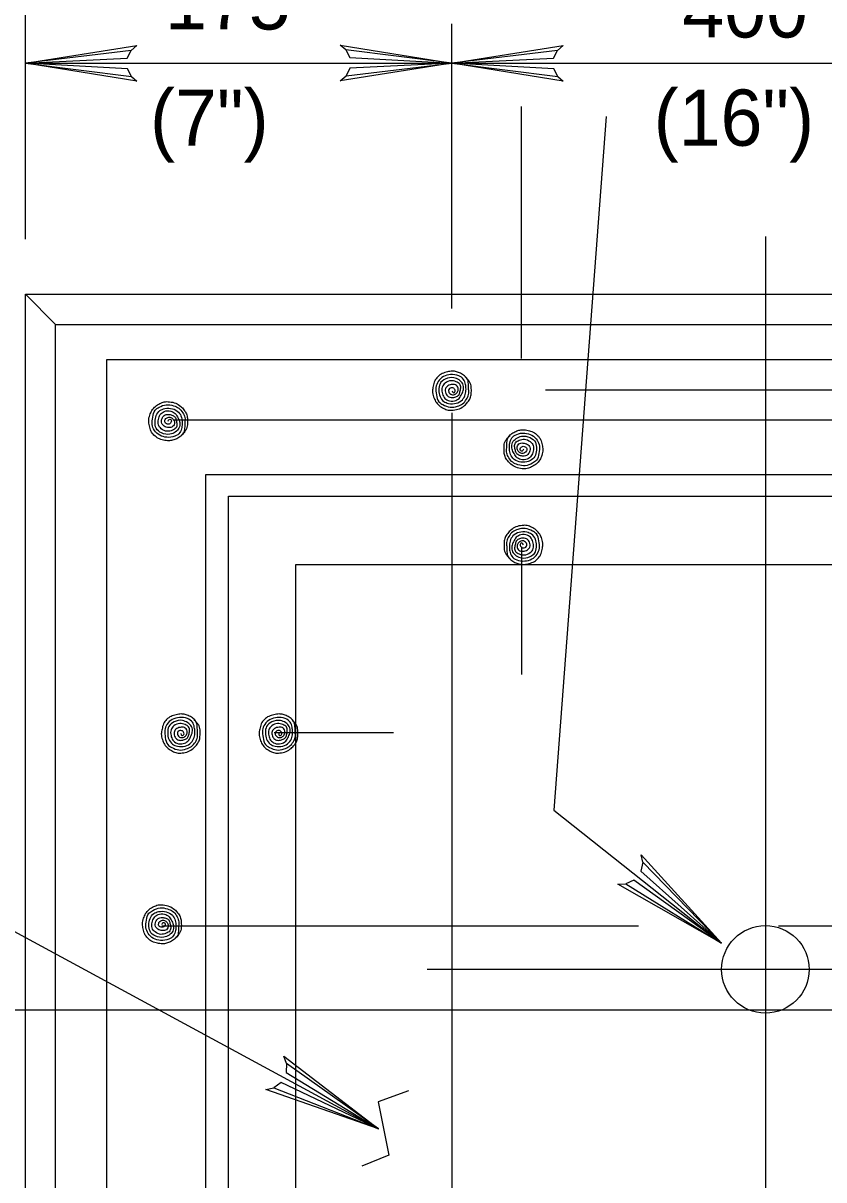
# Model space of a CAD drawing. Extents: x 638455 to 640199, y 298558 to 299152.
# Drawn here: x 639455 to 639502.8, y 299012.9 to 299082 of the extents above; entities that cross this region are included whole.
import ezdxf

# ---------------------------------------------------------------- set-up
doc = ezdxf.new("R2010")
doc.units = 0
for name, color, linetype in [('1', 7, 'Continuous'), ('2', 7, 'Continuous'), ('3', 7, 'Continuous')]:
    doc.layers.add(name, color=color, linetype=linetype)

msp = doc.modelspace()

# ---------------------------------------------------------------- linework, layer by layer
at = {"layer": '1'}
for points in [[(639491.985, 299031.846), (639491.878, 299031.311), (639496.699, 299027.013), (639491.985, 299031.846), (639491.9, 299032.29), (639496.699, 299027.013), (639491.461, 299030.78), (639490.978, 299030.552), (639496.699, 299027.013), (639490.495, 299030.528), (639490.978, 299030.552)], [(639470.711, 299019.827), (639470.701, 299019.282), (639476.213, 299015.916), (639470.711, 299019.827), (639470.548, 299020.249), (639476.213, 299015.916), (639470.386, 299018.685), (639469.952, 299018.374), (639476.213, 299015.916), (639469.481, 299018.263), (639469.952, 299018.374)], [(639478.001, 299018.178), (639476.18, 299017.527), (639476.83, 299014.338), (639475.204, 299013.687)]]:
    msp.add_lwpolyline(points, dxfattribs=at)
at = {"layer": '2'}
for p, q in [((639455.114, 299069.069), (639455.114, 299092.486)), ((639480.579, 299064.94), (639480.579, 299081.944)), ((639455.114, 299079.596), (639480.579, 299079.596)), ((639480.579, 299079.596), (639518.052, 299079.596)), ((639484.748, 299061.942), (639484.748, 299077.013)), ((639489.813, 299076.401), (639486.672, 299034.951)), ((639499.316, 299069.23), (639499.316, 298997.046)), ((639456.919, 299063.987), (639455.114, 299065.791)), ((639455.114, 298964.165), (639455.114, 299065.791)), ((639455.114, 299065.791), (639543.517, 299065.791)), ((639456.919, 298964.165), (639456.919, 299063.987)), ((639459.977, 298949.406), (639459.977, 299061.884)), ((639486.183, 299060.066), (639511.411, 299060.066)), ((639463.941, 299058.292), (639535.345, 299058.292)), ((639480.579, 299058.705), (639480.579, 299000.251)), ((639465.9, 299055.006), (639532.731, 299055.006)), ((639465.9, 298956.209), (639465.9, 299055.006)), ((639467.242, 299053.726), (639531.389, 299053.726)), ((639467.242, 298957.614), (639467.242, 299053.726)), ((639484.748, 299050.686), (639484.748, 299043.062)), ((639471.267, 299049.639), (639527.364, 299049.639)), ((639469.97, 299039.596), (639477.095, 299039.596)), ((639486.672, 299034.951), (639496.699, 299027.013)), ((639449.145, 299030.573), (639476.213, 299015.917)), ((639463.258, 299028.043), (639491.743, 299028.043)), ((639500.102, 299028.043), (639535.572, 299028.043)), ((639518.499, 299025.445), (639479.119, 299025.445)), ((639373.945, 299023.031), (639513.286, 299023.031))]:
    msp.add_line(p, q, dxfattribs=at)
for points in [[(639461.445, 299078.803), (639461.207, 299079.259), (639455.114, 299079.596), (639461.445, 299078.803), (639461.767, 299078.524), (639455.114, 299079.596), (639461.204, 299079.897), (639461.425, 299080.351), (639455.114, 299079.596), (639461.767, 299080.652), (639461.425, 299080.351)], [(639474.248, 299080.391), (639474.486, 299079.933), (639480.579, 299079.596), (639474.248, 299080.391), (639473.926, 299080.67), (639480.579, 299079.596), (639474.489, 299079.296), (639474.268, 299078.841), (639480.579, 299079.596), (639473.926, 299078.539), (639474.268, 299078.841)], [(639486.91, 299078.803), (639486.671, 299079.259), (639480.579, 299079.596), (639486.91, 299078.803), (639487.232, 299078.524), (639480.579, 299079.596), (639486.668, 299079.897), (639486.889, 299080.351), (639480.579, 299079.596), (639487.232, 299080.652), (639486.889, 299080.351)], [(639456.919, 299063.987), (639543.517, 299063.987)], [(639459.977, 299061.884), (639511.013, 299061.884)], [(639471.267, 298961.576), (639471.267, 299049.639)]]:
    msp.add_lwpolyline(points, dxfattribs=at)
msp.add_circle((639499.315, 299025.445), 2.614, dxfattribs=at)
for points in [[(639480.597, 299060.023), (639480.658, 299059.907), (639480.746, 299059.922), (639480.763, 299060.104), (639480.603, 299060.2), (639480.406, 299060.104), (639480.415, 299059.922), (639480.522, 299059.808), (639480.746, 299059.791), (639480.896, 299059.907), (639480.972, 299060.096), (639480.862, 299060.343), (639480.621, 299060.398), (639480.354, 299060.317), (639480.211, 299060.148), (639480.229, 299059.864), (639480.362, 299059.681), (639480.603, 299059.614), (639480.818, 299059.657), (639480.995, 299059.765), (639481.071, 299059.951), (639481.117, 299060.192), (639481.062, 299060.416), (639480.853, 299060.558), (639480.531, 299060.621), (639480.185, 299060.479), (639480.011, 299060.238), (639480.011, 299059.907), (639480.121, 299059.625), (639480.362, 299059.44), (639480.746, 299059.416), (639481.018, 299059.567), (639481.184, 299059.832), (639481.283, 299060.104), (639481.236, 299060.433), (639481.018, 299060.665), (639480.702, 299060.799), (639480.197, 299060.72), (639479.88, 299060.441), (639479.813, 299060.058), (639479.88, 299059.681), (639480.101, 299059.385), (639480.394, 299059.265), (639480.853, 299059.274), (639481.216, 299059.483), (639481.387, 299059.791), (639481.434, 299060.116), (639481.402, 299060.398), (639481.292, 299060.7), (639480.995, 299060.915), (639480.513, 299060.982), (639480.086, 299060.862), (639479.77, 299060.566), (639479.639, 299060.218), (639479.671, 299059.777), (639479.813, 299059.364), (639480.054, 299059.19), (639480.478, 299059.036), (639480.92, 299059.1), (639481.228, 299059.242), (639481.463, 299059.515), (639481.591, 299059.8), (639481.591, 299060.104), (639481.576, 299060.433), (639481.501, 299060.741), (639481.344, 299060.915), (639481.103, 299061.066), (639480.862, 299061.156), (639480.621, 299061.191), (639480.319, 299061.147), (639480.011, 299061.048), (639479.747, 299060.854), (639479.564, 299060.604), (639479.474, 299060.29), (639479.43, 299059.997), (639479.497, 299059.657), (639479.619, 299059.385), (639479.837, 299059.135), (639480.101, 299058.966), (639480.362, 299058.868), (639480.676, 299058.859), (639481.042, 299058.949), (639481.344, 299059.135), (639481.53, 299059.332), (639481.686, 299059.582), (639481.742, 299059.843), (639481.75, 299060.148), (639481.686, 299060.479), (639481.591, 299060.63), (639481.387, 299060.854)], [(639463.651, 299058.196), (639463.709, 299058.312), (639463.796, 299058.3), (639463.813, 299058.117), (639463.654, 299058.019), (639463.459, 299058.117), (639463.468, 299058.3), (639463.575, 299058.411), (639463.796, 299058.428), (639463.95, 299058.312), (639464.025, 299058.126), (639463.912, 299057.877), (639463.671, 299057.821), (639463.404, 299057.903), (639463.261, 299058.071), (639463.279, 299058.359), (639463.412, 299058.542), (639463.654, 299058.608), (639463.869, 299058.562), (639464.046, 299058.454), (639464.121, 299058.269), (639464.167, 299058.028), (639464.112, 299057.804), (639463.903, 299057.662), (639463.584, 299057.601), (639463.235, 299057.743), (639463.061, 299057.984), (639463.061, 299058.312), (639463.172, 299058.594), (639463.412, 299058.783), (639463.796, 299058.803), (639464.069, 299058.652), (639464.234, 299058.388), (639464.333, 299058.117), (639464.287, 299057.787), (639464.069, 299057.554), (639463.752, 299057.42), (639463.247, 299057.502), (639462.93, 299057.778), (639462.864, 299058.161), (639462.93, 299058.542), (639463.151, 299058.835), (639463.444, 299058.954), (639463.903, 299058.945), (639464.266, 299058.736), (639464.441, 299058.428), (639464.484, 299058.103), (639464.452, 299057.821), (639464.342, 299057.519), (639464.046, 299057.304), (639463.564, 299057.238), (639463.137, 299057.36), (639462.82, 299057.653), (639462.689, 299058.001), (639462.721, 299058.443), (639462.864, 299058.858), (639463.105, 299059.032), (639463.529, 299059.184), (639463.97, 299059.119), (639464.278, 299058.977), (639464.516, 299058.704), (639464.641, 299058.42), (639464.641, 299058.117), (639464.626, 299057.787), (639464.551, 299057.479), (639464.394, 299057.304), (639464.153, 299057.153), (639463.912, 299057.064), (639463.671, 299057.028), (639463.369, 299057.072), (639463.061, 299057.171), (639462.797, 299057.369), (639462.614, 299057.618), (639462.527, 299057.929), (639462.48, 299058.225), (639462.547, 299058.562), (639462.669, 299058.835), (639462.887, 299059.085), (639463.151, 299059.253), (639463.412, 299059.352), (639463.726, 299059.36), (639464.092, 299059.273), (639464.394, 299059.085), (639464.583, 299058.887), (639464.737, 299058.637), (639464.792, 299058.376), (639464.801, 299058.071), (639464.737, 299057.743), (639464.641, 299057.589), (639464.441, 299057.369)], [(639484.857, 299056.524), (639484.796, 299056.408), (639484.709, 299056.422), (639484.691, 299056.605), (639484.851, 299056.701), (639485.049, 299056.605), (639485.04, 299056.422), (639484.933, 299056.309), (639484.709, 299056.291), (639484.558, 299056.408), (639484.482, 299056.596), (639484.593, 299056.843), (639484.834, 299056.898), (639485.101, 299056.817), (639485.243, 299056.648), (639485.226, 299056.364), (639485.092, 299056.181), (639484.851, 299056.114), (639484.636, 299056.158), (639484.459, 299056.265), (639484.384, 299056.451), (639484.337, 299056.692), (639484.392, 299056.916), (639484.601, 299057.058), (639484.924, 299057.122), (639485.269, 299056.98), (639485.444, 299056.739), (639485.444, 299056.408), (639485.333, 299056.126), (639485.092, 299055.94), (639484.709, 299055.917), (639484.436, 299056.068), (639484.27, 299056.332), (639484.172, 299056.605), (639484.218, 299056.933), (639484.436, 299057.165), (639484.752, 299057.299), (639485.258, 299057.221), (639485.574, 299056.942), (639485.641, 299056.559), (639485.574, 299056.181), (639485.354, 299055.885), (639485.06, 299055.766), (639484.601, 299055.774), (639484.238, 299055.983), (639484.067, 299056.291), (639484.021, 299056.617), (639484.053, 299056.898), (639484.163, 299057.2), (639484.459, 299057.415), (639484.941, 299057.482), (639485.368, 299057.363), (639485.685, 299057.067), (639485.816, 299056.718), (639485.783, 299056.277), (639485.641, 299055.864), (639485.4, 299055.69), (639484.976, 299055.537), (639484.535, 299055.6), (639484.227, 299055.743), (639483.992, 299056.016), (639483.864, 299056.3), (639483.864, 299056.605), (639483.878, 299056.933), (639483.954, 299057.241), (639484.111, 299057.415), (639484.352, 299057.566), (639484.593, 299057.657), (639484.834, 299057.691), (639485.136, 299057.648), (639485.444, 299057.549), (639485.708, 299057.354), (639485.891, 299057.105), (639485.981, 299056.791), (639486.025, 299056.497), (639485.958, 299056.158), (639485.836, 299055.885), (639485.618, 299055.635), (639485.354, 299055.467), (639485.092, 299055.368), (639484.779, 299055.359), (639484.413, 299055.449), (639484.111, 299055.635), (639483.925, 299055.833), (639483.768, 299056.082), (639483.713, 299056.344), (639483.704, 299056.648), (639483.768, 299056.98), (639483.864, 299057.131), (639484.067, 299057.354)], [(639484.857, 299050.806), (639484.796, 299050.922), (639484.709, 299050.907), (639484.691, 299050.725), (639484.851, 299050.629), (639485.049, 299050.725), (639485.04, 299050.907), (639484.933, 299051.021), (639484.709, 299051.038), (639484.558, 299050.922), (639484.482, 299050.733), (639484.593, 299050.486), (639484.834, 299050.431), (639485.101, 299050.513), (639485.243, 299050.681), (639485.226, 299050.966), (639485.092, 299051.149), (639484.851, 299051.215), (639484.636, 299051.172), (639484.459, 299051.064), (639484.384, 299050.878), (639484.337, 299050.638), (639484.392, 299050.414), (639484.601, 299050.272), (639484.924, 299050.208), (639485.269, 299050.35), (639485.444, 299050.591), (639485.444, 299050.922), (639485.333, 299051.204), (639485.092, 299051.39), (639484.709, 299051.413), (639484.436, 299051.262), (639484.27, 299050.998), (639484.172, 299050.725), (639484.218, 299050.397), (639484.436, 299050.164), (639484.752, 299050.031), (639485.258, 299050.109), (639485.574, 299050.388), (639485.641, 299050.771), (639485.574, 299051.149), (639485.354, 299051.445), (639485.06, 299051.564), (639484.601, 299051.555), (639484.238, 299051.346), (639484.067, 299051.038), (639484.021, 299050.713), (639484.053, 299050.431), (639484.163, 299050.129), (639484.459, 299049.914), (639484.941, 299049.848), (639485.368, 299049.967), (639485.685, 299050.263), (639485.816, 299050.611), (639485.783, 299051.053), (639485.641, 299051.465), (639485.4, 299051.639), (639484.976, 299051.793), (639484.535, 299051.729), (639484.227, 299051.587), (639483.992, 299051.314), (639483.864, 299051.03), (639483.864, 299050.725), (639483.878, 299050.397), (639483.954, 299050.089), (639484.111, 299049.914), (639484.352, 299049.763), (639484.593, 299049.673), (639484.834, 299049.639), (639485.136, 299049.682), (639485.444, 299049.781), (639485.708, 299049.975), (639485.891, 299050.225), (639485.981, 299050.539), (639486.025, 299050.832), (639485.958, 299051.172), (639485.836, 299051.445), (639485.618, 299051.695), (639485.354, 299051.863), (639485.092, 299051.962), (639484.779, 299051.971), (639484.413, 299051.88), (639484.111, 299051.695), (639483.925, 299051.497), (639483.768, 299051.248), (639483.713, 299050.986), (639483.704, 299050.681), (639483.768, 299050.35), (639483.864, 299050.199), (639484.067, 299049.975)], [(639464.403, 299039.539), (639464.461, 299039.423), (639464.549, 299039.438), (639464.569, 299039.621), (639464.406, 299039.716), (639464.211, 299039.621), (639464.22, 299039.438), (639464.328, 299039.325), (639464.549, 299039.307), (639464.703, 299039.423), (639464.778, 299039.612), (639464.665, 299039.862), (639464.423, 299039.914), (639464.156, 299039.833), (639464.014, 299039.664), (639464.032, 299039.38), (639464.165, 299039.197), (639464.406, 299039.13), (639464.621, 299039.173), (639464.798, 299039.281), (639464.877, 299039.467), (639464.92, 299039.708), (639464.865, 299039.931), (639464.656, 299040.073), (639464.337, 299040.138), (639463.988, 299039.995), (639463.814, 299039.754), (639463.814, 299039.423), (639463.924, 299039.141), (639464.165, 299038.955), (639464.549, 299038.932), (639464.821, 299039.083), (639464.987, 299039.347), (639465.086, 299039.621), (639465.039, 299039.949), (639464.821, 299040.181), (639464.505, 299040.315), (639463.999, 299040.236), (639463.683, 299039.957), (639463.616, 299039.574), (639463.683, 299039.197), (639463.904, 299038.9), (639464.197, 299038.781), (639464.656, 299038.79), (639465.019, 299038.999), (639465.193, 299039.307), (639465.237, 299039.632), (639465.205, 299039.914), (639465.094, 299040.216), (639464.798, 299040.431), (639464.319, 299040.498), (639463.889, 299040.378), (639463.573, 299040.082), (639463.442, 299039.737), (639463.474, 299039.295), (639463.616, 299038.88), (639463.857, 299038.706), (639464.281, 299038.555), (639464.723, 299038.616), (639465.03, 299038.758), (639465.269, 299039.031), (639465.393, 299039.316), (639465.393, 299039.621), (639465.379, 299039.949), (639465.303, 299040.257), (639465.146, 299040.431), (639464.906, 299040.582), (639464.665, 299040.672), (639464.423, 299040.707), (639464.122, 299040.663), (639463.814, 299040.565), (639463.549, 299040.37), (639463.367, 299040.12), (639463.279, 299039.806), (639463.233, 299039.513), (639463.3, 299039.173), (639463.422, 299038.9), (639463.639, 299038.651), (639463.904, 299038.482), (639464.165, 299038.383), (639464.479, 299038.375), (639464.845, 299038.465), (639465.146, 299038.651), (639465.335, 299038.848), (639465.489, 299039.098), (639465.545, 299039.362), (639465.553, 299039.664), (639465.489, 299039.995), (639465.393, 299040.146), (639465.193, 299040.37)], [(639470.244, 299039.539), (639470.302, 299039.423), (639470.389, 299039.438), (639470.409, 299039.621), (639470.246, 299039.716), (639470.052, 299039.621), (639470.06, 299039.438), (639470.168, 299039.325), (639470.389, 299039.307), (639470.543, 299039.423), (639470.618, 299039.612), (639470.505, 299039.862), (639470.264, 299039.914), (639469.997, 299039.833), (639469.854, 299039.664), (639469.872, 299039.38), (639470.005, 299039.197), (639470.246, 299039.13), (639470.461, 299039.173), (639470.638, 299039.281), (639470.717, 299039.467), (639470.761, 299039.708), (639470.705, 299039.931), (639470.496, 299040.073), (639470.177, 299040.138), (639469.828, 299039.995), (639469.654, 299039.754), (639469.654, 299039.423), (639469.764, 299039.141), (639470.005, 299038.955), (639470.389, 299038.932), (639470.662, 299039.083), (639470.827, 299039.347), (639470.926, 299039.621), (639470.879, 299039.949), (639470.662, 299040.181), (639470.345, 299040.315), (639469.84, 299040.236), (639469.523, 299039.957), (639469.457, 299039.574), (639469.523, 299039.197), (639469.744, 299038.9), (639470.037, 299038.781), (639470.496, 299038.79), (639470.859, 299038.999), (639471.033, 299039.307), (639471.077, 299039.632), (639471.045, 299039.914), (639470.935, 299040.216), (639470.638, 299040.431), (639470.159, 299040.498), (639469.73, 299040.378), (639469.413, 299040.082), (639469.282, 299039.737), (639469.314, 299039.295), (639469.457, 299038.88), (639469.697, 299038.706), (639470.121, 299038.555), (639470.563, 299038.616), (639470.871, 299038.758), (639471.109, 299039.031), (639471.234, 299039.316), (639471.234, 299039.621), (639471.219, 299039.949), (639471.144, 299040.257), (639470.987, 299040.431), (639470.746, 299040.582), (639470.505, 299040.672), (639470.264, 299040.707), (639469.962, 299040.663), (639469.654, 299040.565), (639469.389, 299040.37), (639469.207, 299040.12), (639469.12, 299039.806), (639469.073, 299039.513), (639469.14, 299039.173), (639469.262, 299038.9), (639469.48, 299038.651), (639469.744, 299038.482), (639470.005, 299038.383), (639470.319, 299038.375), (639470.685, 299038.465), (639470.987, 299038.651), (639471.176, 299038.848), (639471.33, 299039.098), (639471.385, 299039.362), (639471.393, 299039.664), (639471.33, 299039.995), (639471.234, 299040.146), (639471.033, 299040.37)], [(639463.279, 299028.136), (639463.337, 299028.252), (639463.424, 299028.238), (639463.444, 299028.055), (639463.282, 299027.959), (639463.087, 299028.055), (639463.096, 299028.238), (639463.203, 299028.351), (639463.424, 299028.368), (639463.578, 299028.252), (639463.654, 299028.063), (639463.54, 299027.816), (639463.299, 299027.761), (639463.032, 299027.843), (639462.89, 299028.011), (639462.907, 299028.296), (639463.041, 299028.478), (639463.282, 299028.545), (639463.497, 299028.502), (639463.674, 299028.395), (639463.752, 299028.209), (639463.796, 299027.967), (639463.741, 299027.744), (639463.532, 299027.601), (639463.212, 299027.538), (639462.864, 299027.68), (639462.689, 299027.921), (639462.689, 299028.252), (639462.8, 299028.534), (639463.041, 299028.72), (639463.424, 299028.743), (639463.697, 299028.592), (639463.863, 299028.327), (639463.961, 299028.055), (639463.915, 299027.727), (639463.697, 299027.494), (639463.381, 299027.361), (639462.875, 299027.439), (639462.559, 299027.718), (639462.492, 299028.101), (639462.559, 299028.478), (639462.78, 299028.775), (639463.073, 299028.894), (639463.532, 299028.885), (639463.895, 299028.676), (639464.069, 299028.368), (639464.112, 299028.043), (639464.08, 299027.761), (639463.97, 299027.459), (639463.674, 299027.244), (639463.195, 299027.178), (639462.765, 299027.297), (639462.448, 299027.593), (639462.318, 299027.939), (639462.35, 299028.383), (639462.492, 299028.795), (639462.733, 299028.97), (639463.157, 299029.123), (639463.598, 299029.059), (639463.906, 299028.917), (639464.145, 299028.644), (639464.269, 299028.36), (639464.269, 299028.055), (639464.255, 299027.727), (639464.179, 299027.419), (639464.022, 299027.244), (639463.782, 299027.093), (639463.54, 299027.004), (639463.299, 299026.968), (639462.997, 299027.012), (639462.689, 299027.111), (639462.425, 299027.306), (639462.242, 299027.555), (639462.155, 299027.869), (639462.109, 299028.162), (639462.176, 299028.502), (639462.297, 299028.775), (639462.515, 299029.025), (639462.78, 299029.193), (639463.041, 299029.292), (639463.354, 299029.3), (639463.72, 299029.21), (639464.022, 299029.025), (639464.211, 299028.827), (639464.365, 299028.577), (639464.42, 299028.313), (639464.429, 299028.011), (639464.365, 299027.68), (639464.269, 299027.529), (639464.069, 299027.306)]]:
    msp.add_spline(points, degree=3, dxfattribs=at)

# ---------------------------------------------------------------- texts
at = {"layer": '1'}
for s, p in [('(7")', (639462.56, 299074.661)), ('(16")', (639492.642, 299074.661))]:
    msp.add_text(s, height=3.36, dxfattribs=at).set_placement(p)
at = {"layer": '3'}
for s, p in [('175', (639463.457, 299081.607)), ('400', (639494.358, 299081.129))]:
    msp.add_text(s, height=3.36, dxfattribs=at).set_placement(p)

doc.saveas('drawing.dxf')
